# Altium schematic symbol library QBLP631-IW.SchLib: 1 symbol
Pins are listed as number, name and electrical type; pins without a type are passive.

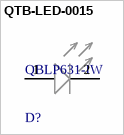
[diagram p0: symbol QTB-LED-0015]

## QTB-LED-0015
designator D?, comment QBLP631-IW
LED WHITE DIFFUSED 0805 SMD; Manufacturer: QT Brightek (QTB); Lens Size: 1.25mm; Luminous Intensity: 270mcd; Test Current: 20mA; Lens Color: Yellow; Lens Style: Flat; Forward Voltage: 3.1V
footprint QBLP631-IW
pins: 1 ANODE (+), 2 CATHODE (-)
